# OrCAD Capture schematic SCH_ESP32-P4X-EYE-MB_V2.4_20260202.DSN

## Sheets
1 01_DESIGNBLOCK: title: ESP32-P4X-EYE-MB; rev: 2.4; note: 01_DESIGNBLOCK
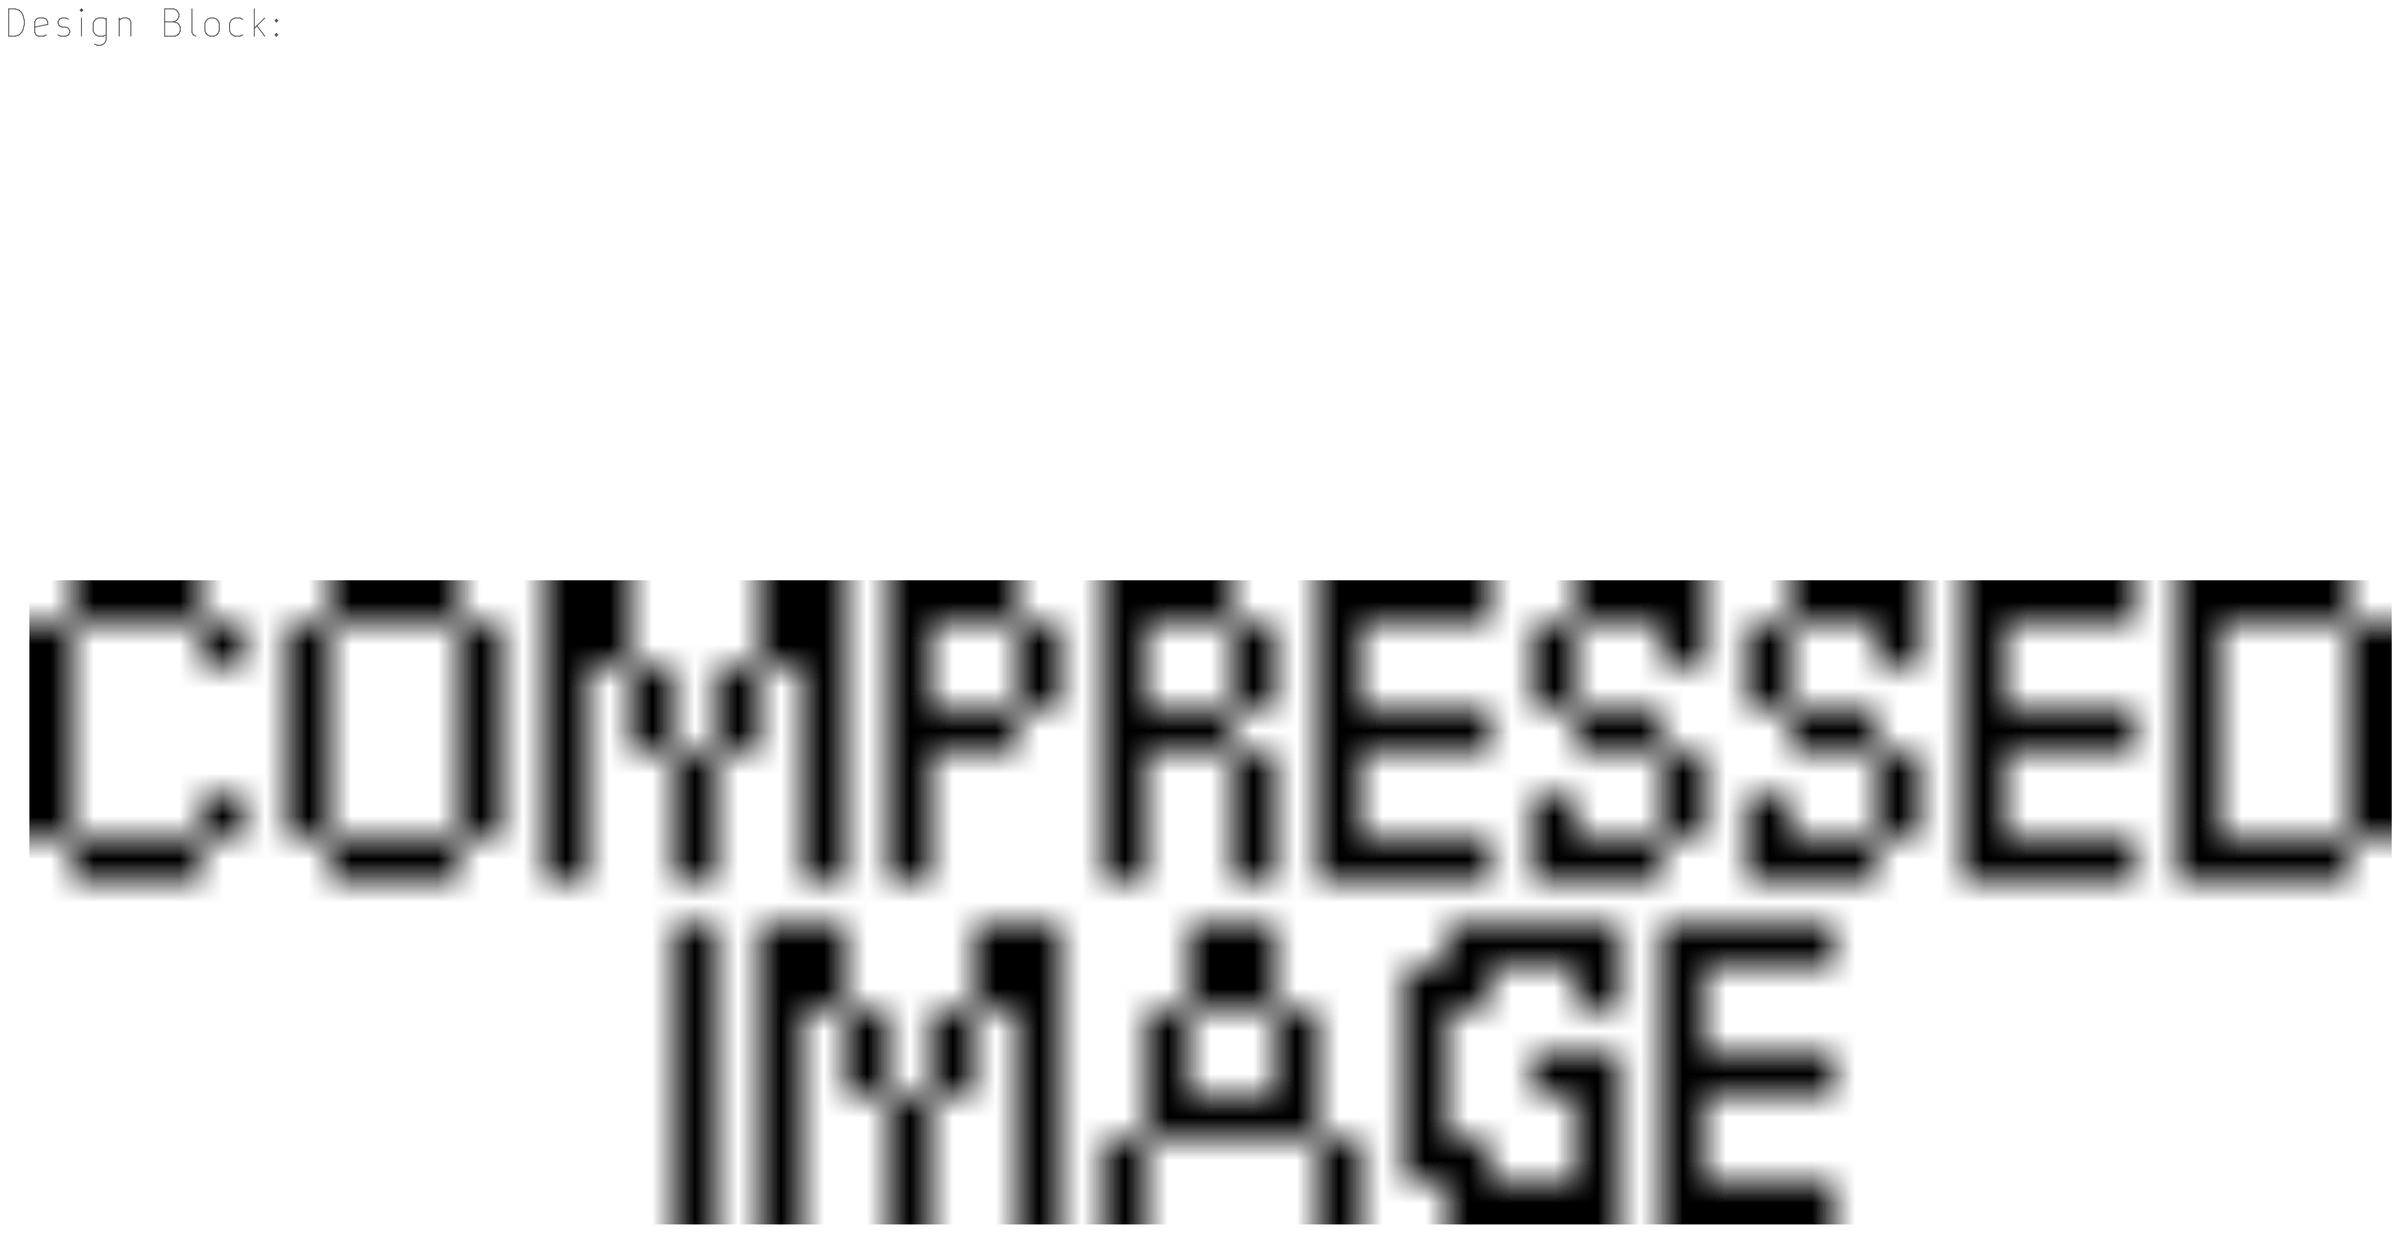
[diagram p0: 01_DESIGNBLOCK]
2 02_ESP32-P4: size C; note: 02_ESP32-P4X
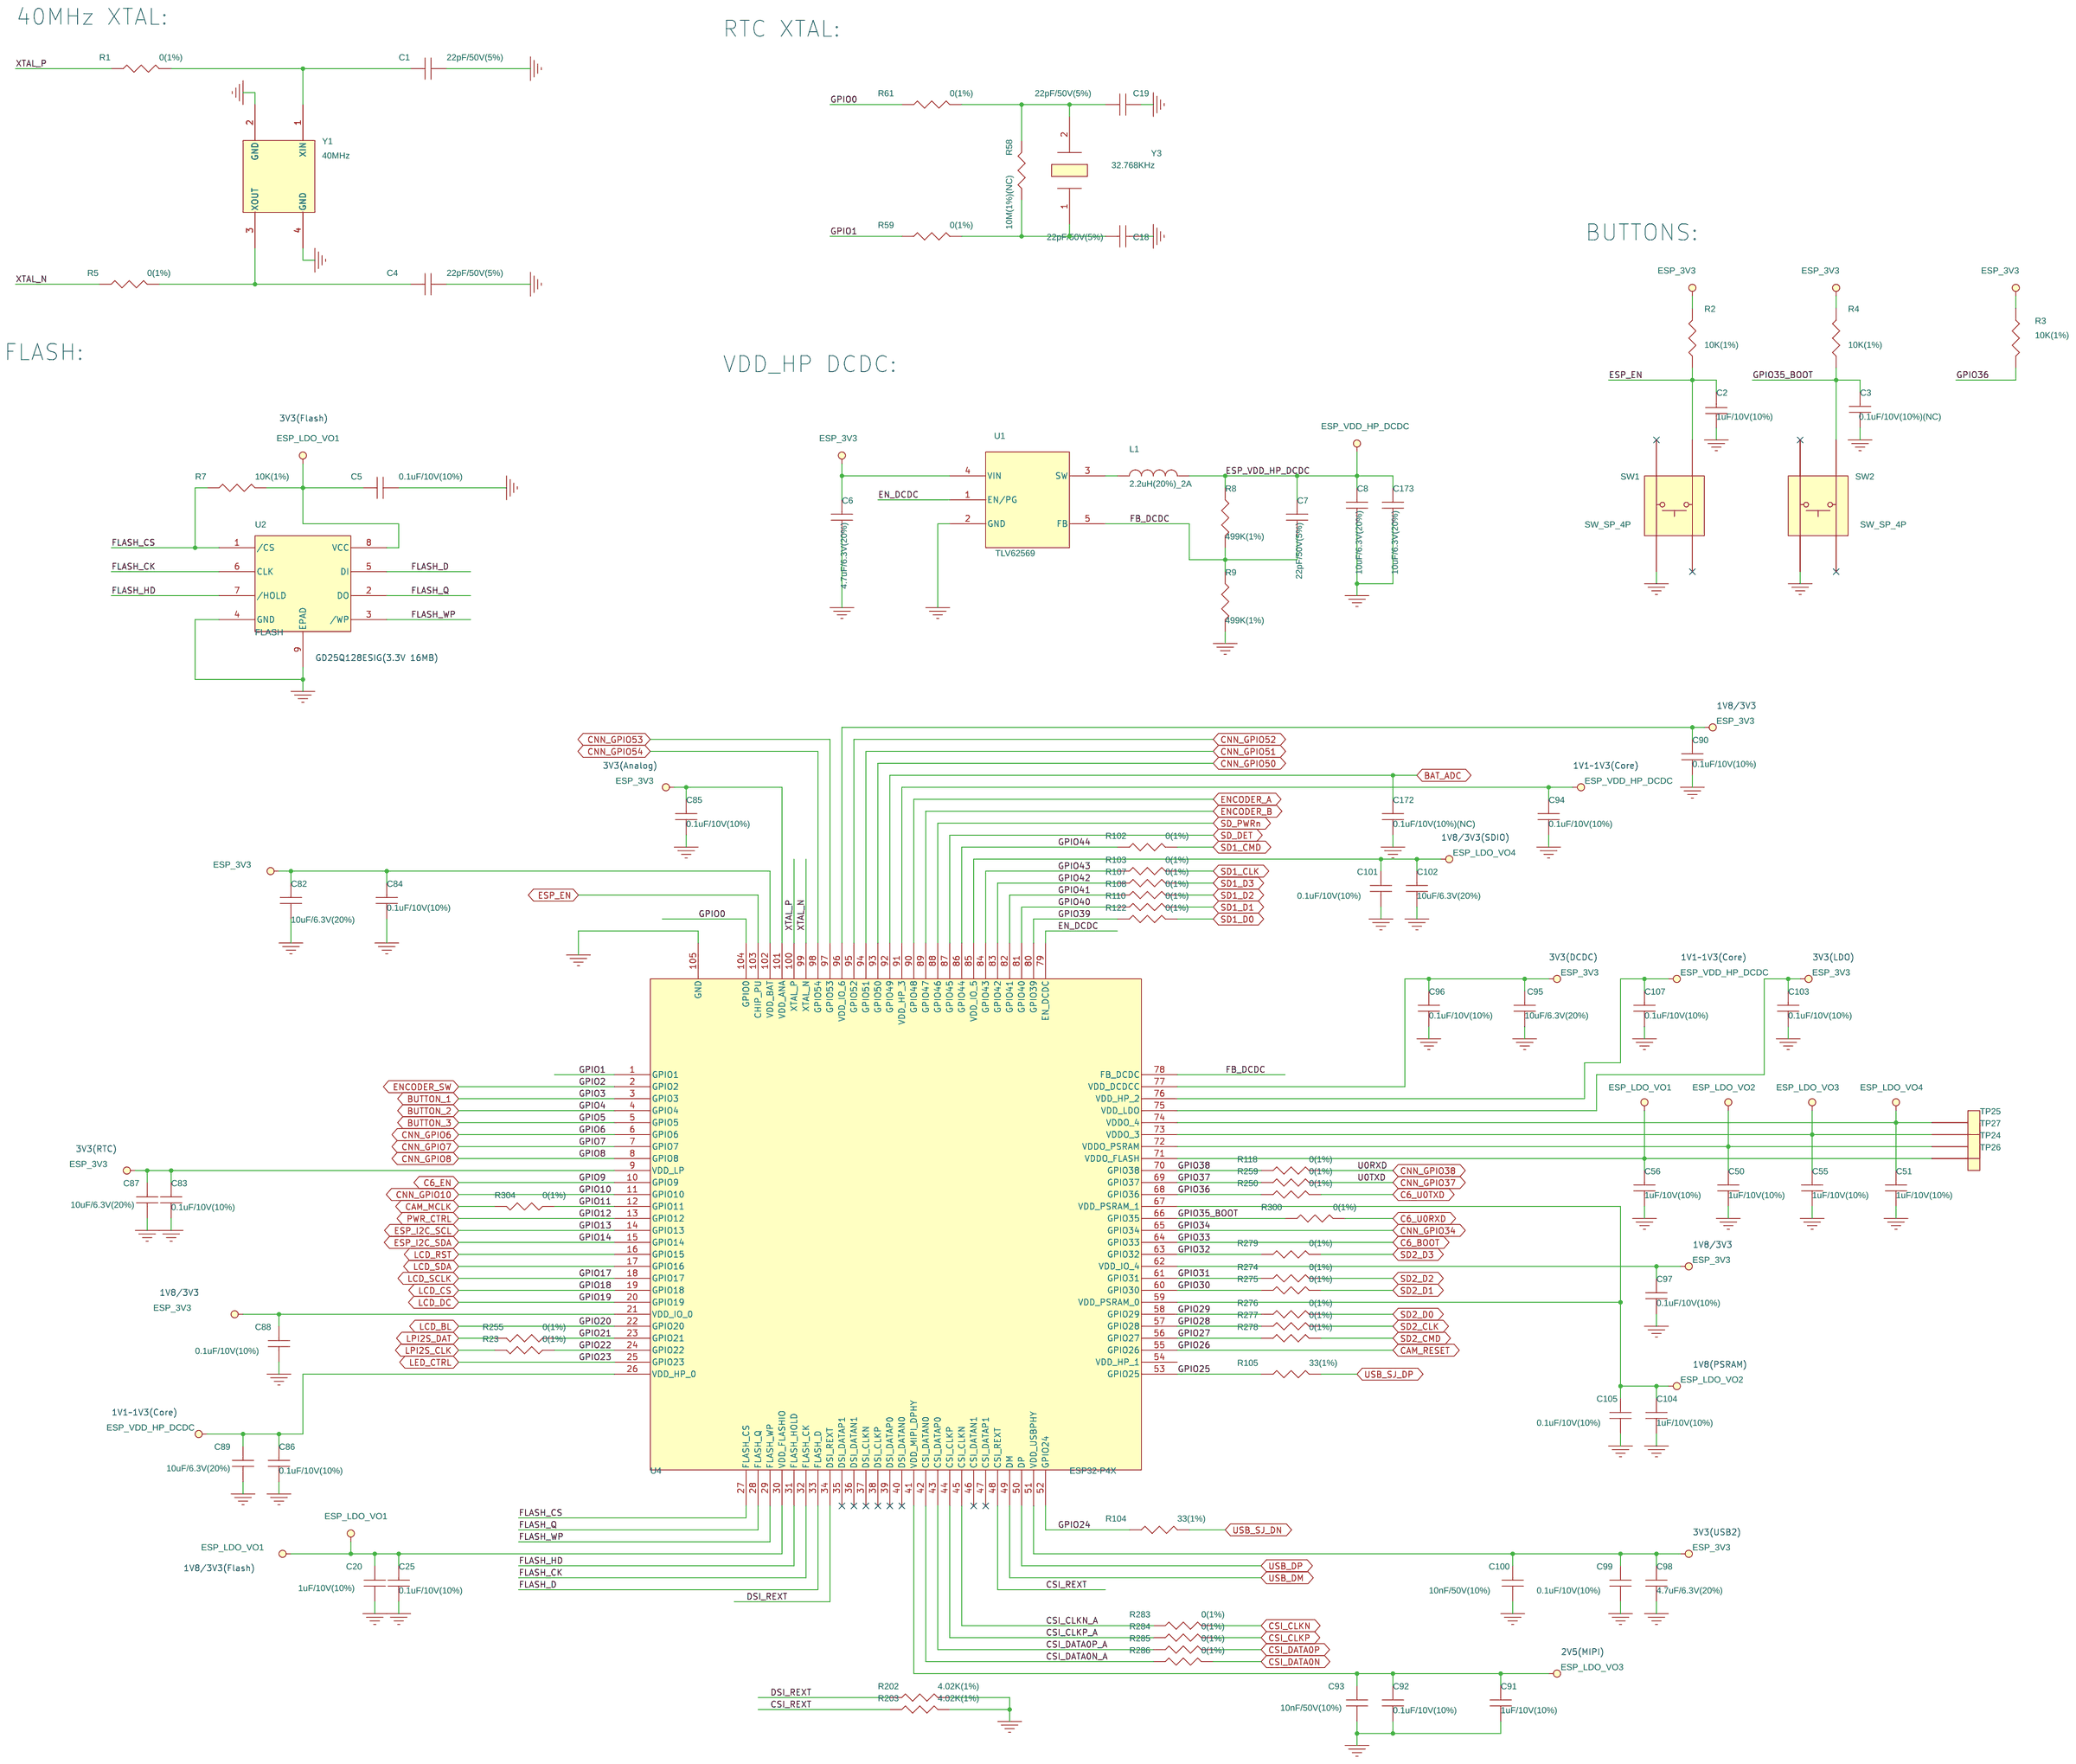
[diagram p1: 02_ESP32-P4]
3 03_INTERFACE: size C; note: 03_INTERFACE
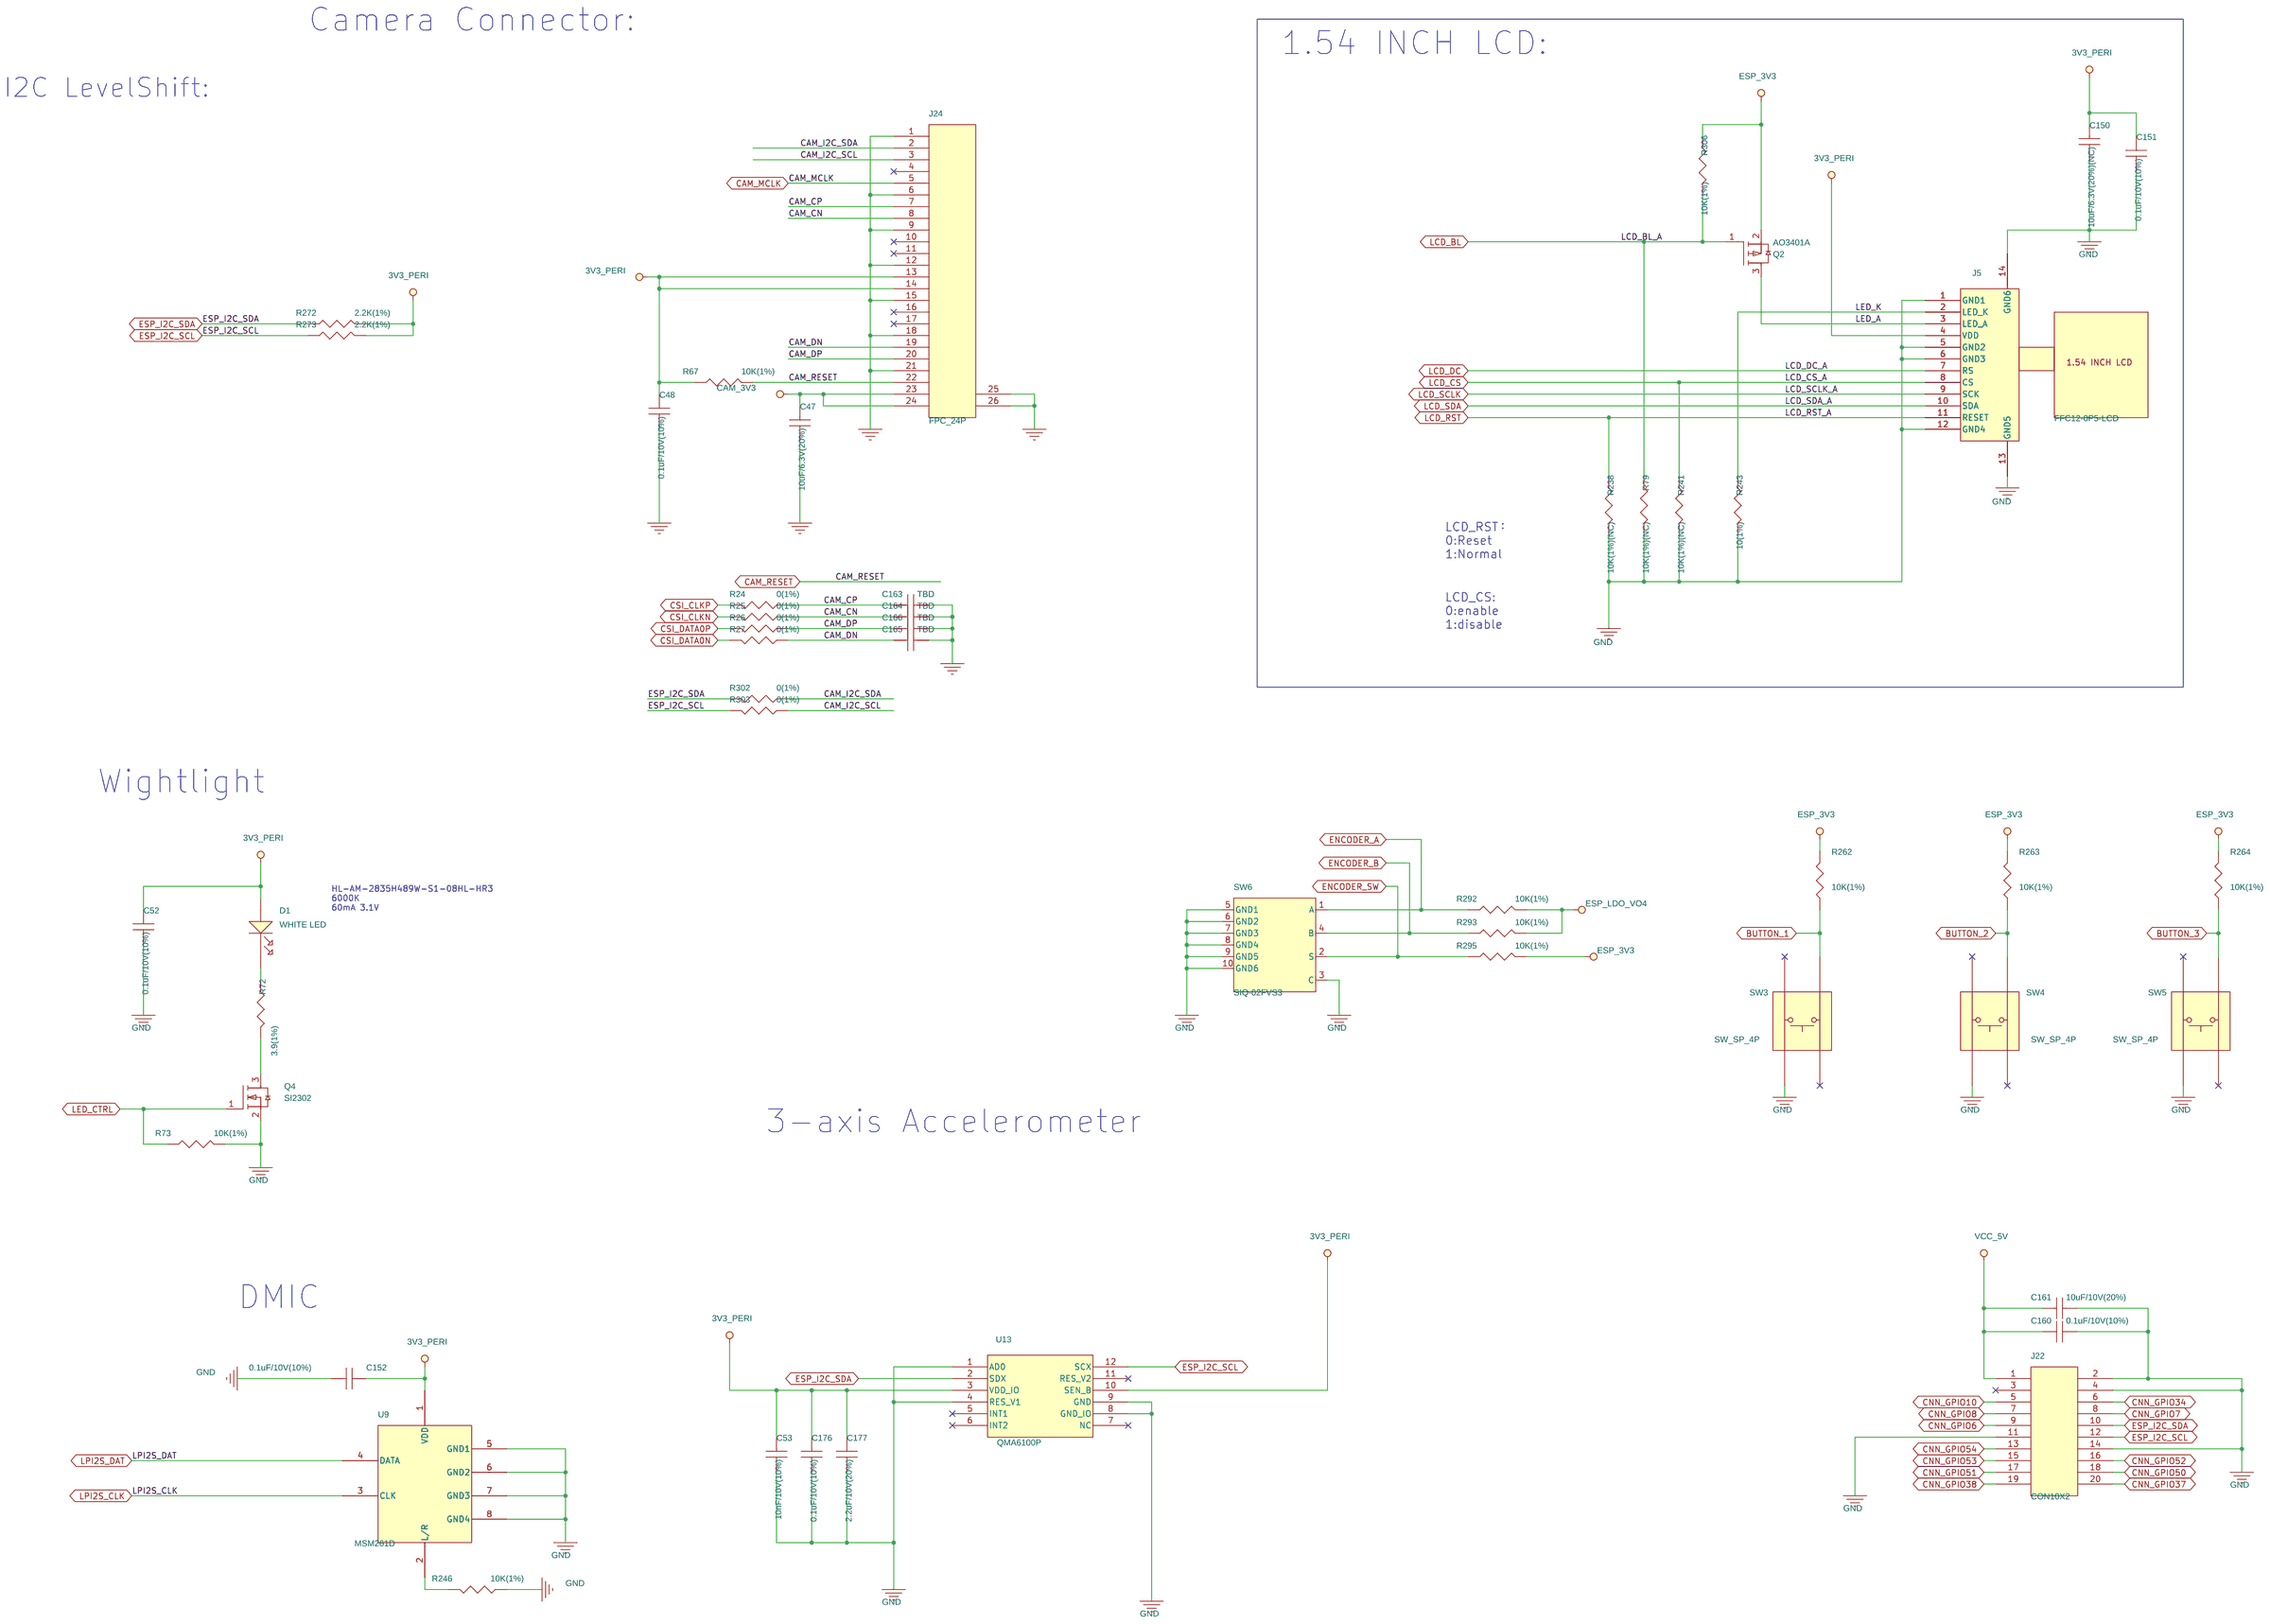
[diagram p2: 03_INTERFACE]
4 04_WiFi&BT_SDCard: size C; note: 04_WiFi&BT
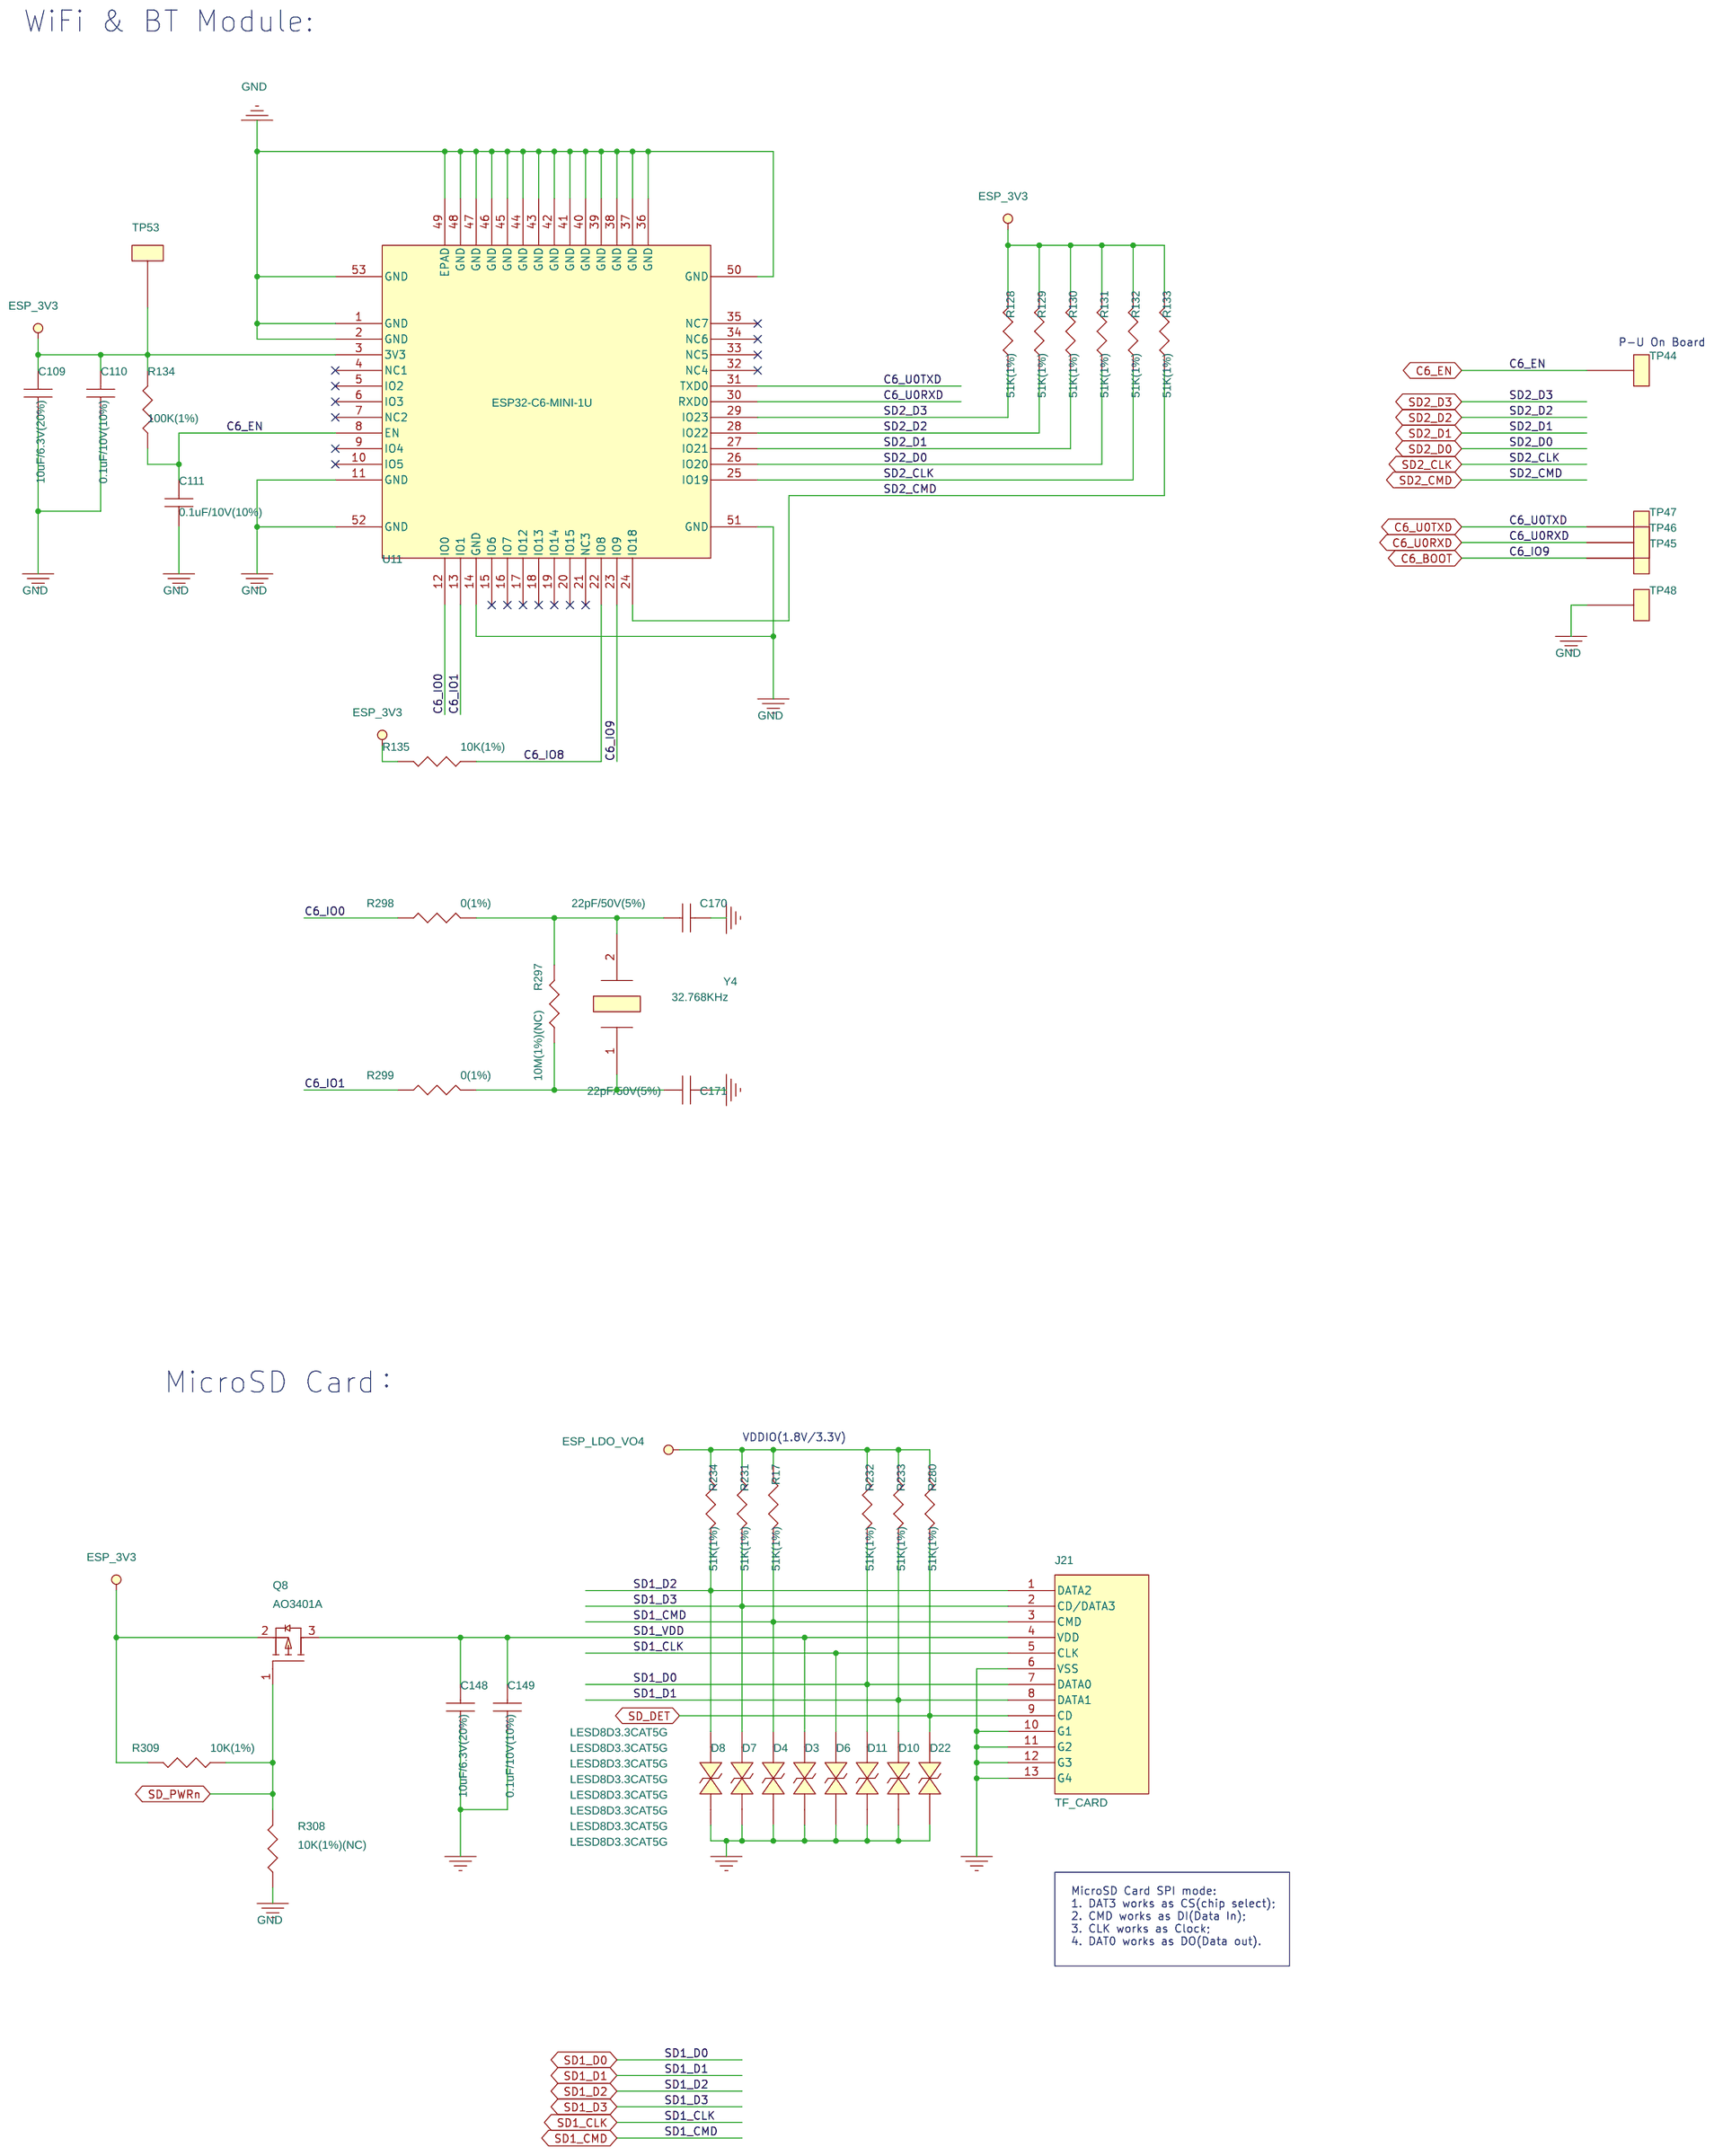
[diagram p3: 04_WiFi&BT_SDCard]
5 05_PWR_USB: size C; note: 05_PWR_USB
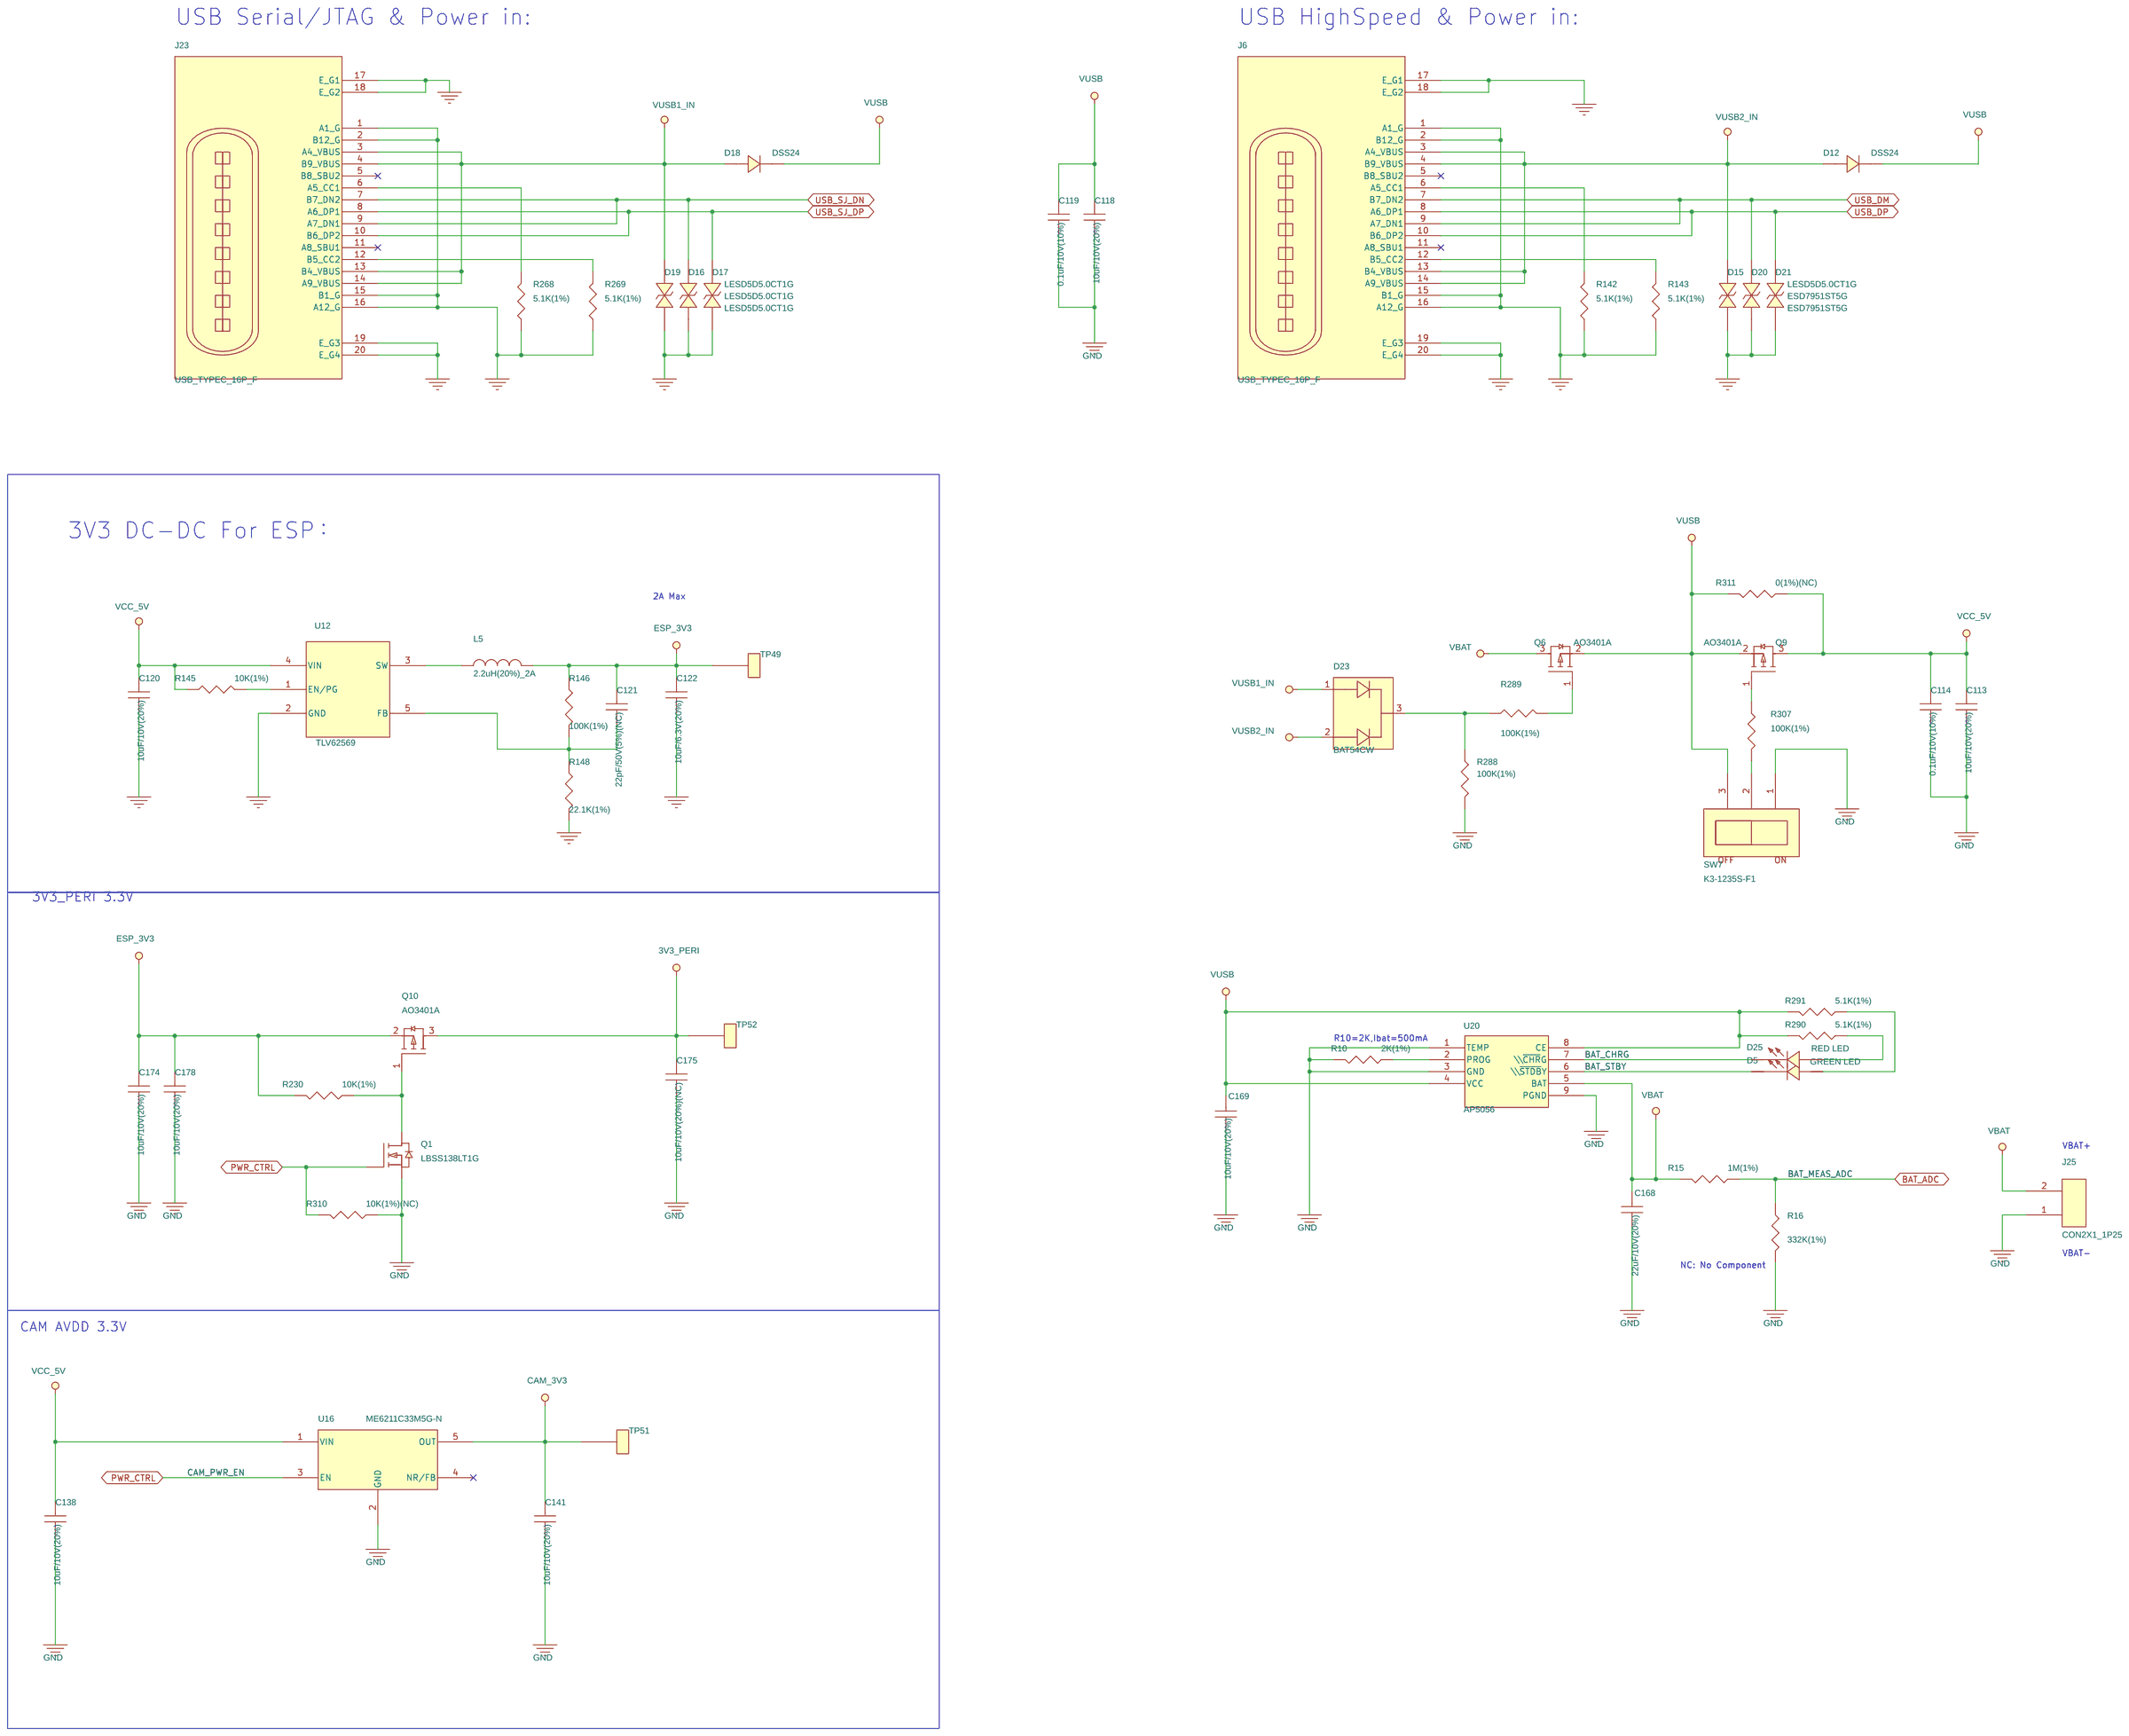
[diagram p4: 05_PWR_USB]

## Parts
sheet 02_ESP32-P4
C1  22pF/50V(5%)  [C0201]
C2  1uF/10V(10%)  [C0402]
C3  0.1uF/10V(10%)(NC)  [C0402]
C4  22pF/50V(5%)  [C0201]
C5  0.1uF/10V(10%)  [C0402]
C6  4.7uF/6.3V(20%)  [C0402]
C7  22pF/50V(5%)  [C0402]
C8  10uF/6.3V(20%)  [C0402]
C18  22pF/50V(5%)  [C0201]
C19  22pF/50V(5%)  [C0201]
C20  1uF/10V(10%)  [C0402]
C25  0.1uF/10V(10%)  [C0402]
C50  1uF/10V(10%)  [C0402]
C51  1uF/10V(10%)  [C0402]
C55  1uF/10V(10%)  [C0402]
C56  1uF/10V(10%)  [C0402]
C82  10uF/6.3V(20%)  [C0402]
C83  0.1uF/10V(10%)  [C0402]
C84  0.1uF/10V(10%)  [C0402]
C85  0.1uF/10V(10%)  [C0402]
C86  0.1uF/10V(10%)  [C0402]
C87  10uF/6.3V(20%)  [C0402]
C88  0.1uF/10V(10%)  [C0402]
C89  10uF/6.3V(20%)  [C0402]
C90  0.1uF/10V(10%)  [C0402]
C91  1uF/10V(10%)  [C0402]
C92  0.1uF/10V(10%)  [C0402]
C93  10nF/50V(10%)  [C0402]
C94  0.1uF/10V(10%)  [C0402]
C95  10uF/6.3V(20%)  [C0402]
C96  0.1uF/10V(10%)  [C0402]
C97  0.1uF/10V(10%)  [C0402]
C98  4.7uF/6.3V(20%)  [C0402]
C99  0.1uF/10V(10%)  [C0402]
C100  10nF/50V(10%)  [C0402]
C101  0.1uF/10V(10%)  [C0402]
C102  10uF/6.3V(20%)  [C0402]
C103  0.1uF/10V(10%)  [C0402]
C104  1uF/10V(10%)  [C0402]
C105  0.1uF/10V(10%)  [C0402]
C107  0.1uF/10V(10%)  [C0402]
C172  0.1uF/10V(10%)(NC)  [C0201]
C173  10uF/6.3V(20%)  [C0402]
L1  2.2uH(20%)_2A  [L2520]
R1  0(1%)  [R0201]
R2  10K(1%)  [R0201]
R3  10K(1%)  [R0201]
R4  10K(1%)  [R0201]
R5  0(1%)  [R0201]
R7  10K(1%)  [R0201]
R8  499K(1%)  [R0402]
R9  499K(1%)  [R0402]
R23  0(1%)  [R0201]
R58  10M(1%)(NC)  [R0201]
R59  0(1%)  [R0201]
R61  0(1%)  [R0201]
R102  0(1%)  [R0201]
R103  0(1%)  [R0201]
R104  33(1%)  [R0201]
R105  33(1%)  [R0201]
R107  0(1%)  [R0201]
R108  0(1%)  [R0201]
R110  0(1%)  [R0201]
R118  0(1%)  [R0201]
R122  0(1%)  [R0201]
R202  4.02K(1%)  [R0201]
R203  4.02K(1%)  [R0201]
R250  0(1%)  [R0201]
R255  0(1%)  [R0201]
R259  0(1%)  [R0201]
R274  0(1%)  [R0201]
R275  0(1%)  [R0201]
R276  0(1%)  [R0201]
R277  0(1%)  [R0201]
R278  0(1%)  [R0201]
R279  0(1%)  [R0201]
R283  0(1%)  [R0201]
R284  0(1%)  [R0201]
R285  0(1%)  [R0201]
R286  0(1%)  [R0201]
R300  0(1%)  [R0201]
R304  0(1%)  [R0201]
SW1  SW_SP_4P  [sw4-4p2x3p2x2p5-smt]
SW2  SW_SP_4P  [sw4-4p2x3p2x2p5-smt]
TP24  TESTPOINT  [TPC1]
TP25  TESTPOINT  [TPC1]
TP26  TESTPOINT  [TPC1]
TP27  TESTPOINT  [TPC1]
U1  TLV62569  [sot23_0P95_2P6]
U2  FLASH  [WSON8_1p27_6x5_e4x3p4]
U4  ESP32-P4X  [qfn104_0p35_10_e7p5_a]
Y1  40MHz  [XTAL3225]
Y3  32.768KHz  [XTAL3215_2P]
sheet 03_INTERFACE
C47  10uF/6.3V(20%)  [C0402]
C48  0.1uF/10V(10%)  [C0201]
C52  0.1uF/10V(10%)  [C0402]
C53  10nF/10V(10%)  [C0201]
C150  10uF/6.3V(20%)(NC)  [C0402]
C151  0.1uF/10V(10%)  [C0402]
C152  0.1uF/10V(10%)  [C0201]
C160  0.1uF/10V(10%)  [C0402]
C161  10uF/10V(20%)  [C0603]
C163  TBD  [C0201]
C164  TBD  [C0201]
C165  TBD  [C0201]
C166  TBD  [C0201]
C176  0.1uF/10V(10%)  [C0201]
C177  2.2uF/10V(20%)  [C0402]
D1  WHITE LED  [LED2835]
J5  FFC12-0P5-LCD  [FFC12_0P5_AFC24-S12FIC-00]
J22  CON10X2  [con10x2_2p54_smt_r]
J24  FPC_24P  [FFC24_0P5_FPC-05FB-24PH20]
Q2  AO3401A  [SOT23-3]
Q4  SI2302  [SOT23-3]
R24  0(1%)  [R0201]
R25  0(1%)  [R0201]
R26  0(1%)  [R0201]
R27  0(1%)  [R0201]
R67  10K(1%)  [R0201]
R72  3.9(1%)  [R0402]
R73  10K(1%)  [R0201]
R79  10K(1%)(NC)  [R0201]
R238  10K(1%)(NC)  [R0201]
R241  10K(1%)(NC)  [R0201]
R243  10(1%)  [R0402]
R246  10K(1%)  [R0201]
R262  10K(1%)  [R0201]
R263  10K(1%)  [R0201]
R264  10K(1%)  [R0201]
R272  2.2K(1%)  [R0201]
R273  2.2K(1%)  [R0201]
R292  10K(1%)  [R0201]
R293  10K(1%)  [R0201]
R295  10K(1%)  [R0201]
R302  0(1%)  [R0201]
R303  0(1%)  [R0201]
R306  10K(1%)  [R0201]
SW3  SW_SP_4P  [sw4-4p2x3p2x2p5-smt]
SW4  SW_SP_4P  [sw4-4p2x3p2x2p5-smt]
SW5  SW_SP_4P  [sw4-4p2x3p2x2p5-smt]
SW6  SIQ-02FVS3  [SIQ-02FVS3]
U9  MSM261D  [OCLGA-8]
U13  QMA6100P  [LGA12_0P5_2]
sheet 04_WiFi&BT_SDCard
C109  10uF/6.3V(20%)  [C0402]
C110  0.1uF/10V(10%)  [C0402]
C111  0.1uF/10V(10%)  [C0402]
C148  10uF/6.3V(20%)  [C0402]
C149  0.1uF/10V(10%)  [C0402]
C170  22pF/50V(5%)  [C0201]
C171  22pF/50V(5%)  [C0201]
D3  LESD8D3.3CAT5G  [SOD882]
D4  LESD8D3.3CAT5G  [SOD882]
D6  LESD8D3.3CAT5G  [SOD882]
D7  LESD8D3.3CAT5G  [SOD882]
D8  LESD8D3.3CAT5G  [SOD882]
D10  LESD8D3.3CAT5G  [SOD882]
D11  LESD8D3.3CAT5G  [SOD882]
D22  LESD8D3.3CAT5G  [SOD882]
J21  TF_CARD  [tf_carda]
Q8  AO3401A  [SOT23-3]
R17  51K(1%)  [R0201]
R128  51K(1%)  [R0201]
R129  51K(1%)  [R0201]
R130  51K(1%)  [R0201]
R131  51K(1%)  [R0201]
R132  51K(1%)  [R0201]
R133  51K(1%)  [R0201]
R134  100K(1%)  [R0201]
R135  10K(1%)  [R0201]
R231  51K(1%)  [R0201]
R232  51K(1%)  [R0201]
R233  51K(1%)  [R0201]
R234  51K(1%)  [R0201]
R280  51K(1%)  [R0201]
R297  10M(1%)(NC)  [R0201]
R298  0(1%)  [R0201]
R299  0(1%)  [R0201]
R308  10K(1%)(NC)  [R0201]
R309  10K(1%)  [R0201]
TP44  TESTPOINT  [TPC1]
TP45  TESTPOINT  [TPC1]
TP46  TESTPOINT  [TPC1]
TP47  TESTPOINT  [TPC1]
TP48  TESTPOINT  [TPC1]
TP53  TESTPOINT  [TPC1]
U11  ESP32-C6-MINI-1U  [ESP32-C6-MINI-1U]
Y4  32.768KHz  [XTAL3215_2P]
sheet 05_PWR_USB
C113  10uF/10V(20%)  [C0603]
C114  0.1uF/10V(10%)  [C0402]
C118  10uF/10V(20%)  [C0603]
C119  0.1uF/10V(10%)  [C0402]
C120  10uF/10V(20%)  [C0603]
C121  22pF/50V(5%)(NC)  [C0402]
C122  10uF/6.3V(20%)  [C0402]
C138  10uF/10V(20%)  [C0603]
C141  10uF/10V(20%)  [C0603]
C168  22uF/10V(20%)  [C0603]
C169  10uF/10V(20%)  [C0603]
C174  10uF/10V(20%)  [C0603]
C175  10uF/10V(20%)(NC)  [C0603]
C178  10uF/10V(20%)  [C0603]
D5  GREEN LED  [LED0603]
D12  DSS24  [SOD123FL]
D15  LESD5D5.0CT1G  [SOD523]
D16  LESD5D5.0CT1G  [SOD523]
D17  LESD5D5.0CT1G  [SOD523]
D18  DSS24  [SOD123FL]
D19  LESD5D5.0CT1G  [SOD523]
D20  ESD7951ST5G  [SOD882]
D21  ESD7951ST5G  [SOD882]
D23  BAT54CW  [SOT323]
D25  RED LED  [LED0603]
J6  USB_TYPEC_16P_F  [USB_TYPEC_16P_F]
J23  USB_TYPEC_16P_F  [USB_TYPEC_16P_F]
J25  CON2X1_1P25  [gh2_1p25_r]
L5  2.2uH(20%)_2A  [L2520]
Q1  LBSS138LT1G  [SOT23-3]
Q6  AO3401A  [SOT23-3]
Q9  AO3401A  [SOT23-3]
Q10  AO3401A  [SOT23-3]
R10  2K(1%)  [R0402]
R15  1M(1%)  [R0402]
R16  332K(1%)  [R0402]
R142  5.1K(1%)  [R0201]
R143  5.1K(1%)  [R0201]
R145  10K(1%)  [R0402]
R146  100K(1%)  [R0402]
R148  22.1K(1%)  [R0402]
R230  10K(1%)  [R0201]
R268  5.1K(1%)  [R0201]
R269  5.1K(1%)  [R0201]
R288  100K(1%)  [R0201]
R289  100K(1%)  [R0201]
R290  5.1K(1%)  [R0402]
R291  5.1K(1%)  [R0402]
R307  100K(1%)  [R0402]
R310  10K(1%)(NC)  [R0201]
R311  0(1%)(NC)  [R0603]
SW7  K3-1235S-F1  [SW3-9p1x3p5x5p5-smt]
TP49  TESTPOINT  [TPC1]
TP51  TESTPOINT  [TPC1]
TP52  TESTPOINT  [TPC1]
U12  TLV62569  [sot23_0P95_2P6]
U16  ME6211C33M5G-N  [SOT23-5]
U20  AP5056  [SOP8_1P27_4P9X3P9_E3P3X2P4]

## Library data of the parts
C1 C4 C7 C18 C19 C121 C170 C171 = CAPACITOR: Part Number: ES110412265200; Part Type: Capacitor
C2 C3 C5 C25 C83-C86 C88 C90 C92 C94 C96 C97 C99 C101 C103 C105 C107 C110 C149 C172 = CAPACITOR: Part Number: ES110451066200; Part Type: Capacitor
C6 C8 C20 C82 C87 C89 C91 C93 C95 C98 C100 C102 C104 C120 C122 C173 = CAP
C50 C51 C55 C56 C111 = CAPACITOR: Part Number: ES110461046100; Part Type: Capacitor
L1 L5 = INDUCTOR
R1 R5 R24-R27 R302-R304 = RESISTOR: Part Number: ES210400000000; Part Type: Resistor
R2-R4 R7 R67 R128-R135 R262-R264 R292 R293 R295 = RESISTOR: Part Number: ES210441000000; Part Type: Resistor
R8 R9 R23 R59 R61 R102-R105 R107 R108 R110 R118 R122 R146 R148 R202 R203 R243 R250 R255 R259 R272-R279 R283-R286 R298-R300 = RESISTOR
R58 R297 = RESISTOR: Part Number: ES210471000000; Part Type: Resistor
SW1-SW5 = SW_SP_4P
TP24-TP27 = TESTPOINT: Part Number: ES519900000000
U1 U12 = TLV62565
U2 = FLASH_EPAD
U4 = ESP32-P4_QFN104_ECO6
Y1 = XTAL
Y3 Y4 = XTAL_2P
C47 C48 C148 C160 C163-C166 = CAPACITOR
C52 = CAPACITOR: CODE12: ES11.04.510.2.6.2.00; Part Number: ES11045102620001; Part Type: Capacitor
C53 = CAPACITOR: CODE12: ES11.02.410.3.6.0.00; Part Number: ES11024103600001; Part Type: Capacitor
C150 C161 = CAPACITOR: CODE12: ES11.06.710.4.7.0.00; Part Number: ES11067104700001; Part Type: Capacitor
C114 C119 C151 = CAPACITOR: CODE12: ES11.04.510.3.6.2.00; Part Number: ES11045103620000; Part Type: Capacitor
C152 C168 C169 = CAP_NP
C176 = CAPACITOR: CODE12: ES11.02.510.3.6.1.00; Part Number: ES11025103610001; Part Type: Capacitor
C177 = CAPACITOR: CODE12: ES11.04.647.3.6.0.00; Part Number: ES11046473600001; Part Type: Capacitor
D1 = DIODE_LIGHT: Part Number: ES313400100000; Part Type: Diode
J5 = FFC12-0P5-LCD_3
J22 = CON10X2
J24 = FPC_24P
Q2 = PMOS: CODE12: ES31.46.0000.00.0.0; Part Number: ES31460000000000; Part Type: Transistor
Q4 = NMOS
R72 = RESISTOR: CODE12: ES21.02.1510.0.00.0; Part Number: ES21021510000001; Part Type: Resistor
R73 = RESISTOR: CODE12: ES21.02.4100.0.00.0; Part Number: ES21024100000001; Part Type: Resistor
R79 R238 R241 R306 = RESISTOR: CODE12: ES21.02.3200.0.00.0; Part Number: ES21023200000001; Part Type: Resistor
R10 R15 R16 R246 R288-R291 R307 = RESISTOR_0
SW6 = Encoder
U9 = NSM0418DT
U13 = QMA7981_0
C109 = CAPACITOR: Part Number: ES110671057000; Part Type: Capacitor
D3 D4 D6-D8 D10 D11 D22 = DIODE_BI_DIR: Part Number: ES313200100000; Part Type: Diode
J21 = TF_SD_SOCKET
Q8 Q10 = PMOS
R17 R231-R234 R280 = RESISTOR: Part Number: ES210445100000; Part Type: Resistor
R230 R308-R311 = RESISTOR: Part Number: ES210600000000; Part Type: Resistor
TP44-TP49 TP51-TP53 = TESTPOINT: CODE12: ES51.99.0010.00.00; Part Number: ES51990010000000
U11 = ESP32-C6-MINI-1
C113 C118 C138 C141 C174 C175 C178 = CAPACITOR: CODE12: ES11.06.710.4.6.0.00; Part Number: ES11067104600000; Part Type: Capacitor
D5 D25 = LED_1
D12 D18 = DIODE_S: CODE12: ES31.30.0020.00.0.0; Part Number: ES31300150000000; Part Type: Diode
D15-D17 D19-D21 = DIODE_BI_DIR: CODE12: ES31.32.0020.00.0.0; Part Number: ES31320020000000; Part Type: Diode
D23 = BAT54C_0
J6 J23 = USB_TYPEC_16P_F: CODE12: ES52.22.0020.00.00; Part Number: ES52220020000000; Part Type: Connector
J25 = CON2X1
Q1 = MOSFET_EN_DGS_0
Q6 Q9 = PMOS_0: CODE12: ES31.46.0000.00.0.0; Part Number: ES31460000000000; Part Type: Transistor
R142 R143 R268 R269 = RESISTOR: Part Number: ES210435100000; Part Type: Resistor
R145 = RESISTOR: Part Number: ES210451000000; Part Type: Resistor
SW7 = SS-12D10L3
U16 = LDO_SOT23-5_3: CODE12: ES41.14.02.07.00.00; Part Number: ES41140207000000; Part Type: Power ICs
U20 = AP5056

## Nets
3V3_PERI: C48.1 C52.1 C53.1 C150.1 C151.1 C152.1 C175.1 C176.1 C177.1 D1.1(ANODE) J5.4(VDD) J24.13 J24.14 Q10.3(D) R67.1 R272.2 R273.2 TP52.1 U9.1(VDD) U13.3(VDD_IO) U13.10(SEN_B)
GND: C1.2 C2.1 C3.2 C4.2 C5.2 C6.2 C8.2 C18.2 C19.2 C20.2 C25.2 C47.2 C48.2 C50.2 C51.2 C52.2 C53.2 C55.2 C56.2 C82.2 C83.2 C84.2 C85.2 C86.2 C87.2 C88.2 C89.2 C90.2 C91.2 C92.2 C93.2 C94.2 C95.2 C96.2 C97.2 C98.2 C99.2 C100.2 C101.2 C102.2 C103.2 C104.2 C105.2 C107.2 C109.2 C110.2 C111.2 C113.2 C114.2 C118.2 C119.2 C120.2 C122.2 C138.2 C141.2 C148.2 C149.2 C150.2 C151.2 C152.2 C160.2 C161.2 C163.2 C164.2 C165.2 C166.2 C168.1 C169.1 C170.2 C171.2 C172.2 C173.2 C174.2 C175.2 C176.2 C177.2 C178.2 D3.1 D4.1 D6.1 D7.1 D8.1 D10.1 D11.1 D15.1 D16.1 D17.1 D19.1 D20.1 D21.1 D22.1 J5.1(GND1) J5.5(GND2) J5.6(GND3) J5.12(GND4) J5.13(GND5) J5.14(GND6) J6.1(A1_G) J6.2(B12_G) J6.15(B1_G) J6.16(A12_G) J6.17(E_G1) J6.18(E_G2) J6.19(E_G3) J6.20(E_G4) J21.6(VSS) J21.10(G1) J21.11(G2) J21.12(G3) J21.13(G4) J22.2 J22.4 J22.11 J22.14 J23.1(A1_G) J23.2(B12_G) J23.15(B1_G) J23.16(A12_G) J23.17(E_G1) J23.18(E_G2) J23.19(E_G3) J23.20(E_G4) J24.1 J24.6 J24.9 J24.12 J24.15 J24.18 J24.21 J24.25 J24.26 J25.1 Q1.2(S) Q4.2(S) R9.2 R10.2 R16.2 R73.2 R79.2 R142.1 R143.1 R148.2 R202.2 R203.2 R238.2 R241.2 R243.2 R246.1 R268.1 R269.1 R288.2 R308.1 R310.1 SW1.1 SW2.1 SW3.1 SW4.1 SW5.1 SW6.3(C) SW6.5(GND1) SW6.6(GND2) SW6.7(GND3) SW6.8(GND4) SW6.9(GND5) SW6.10(GND6) SW7.1 TP48.1 U1.2(GND) U2.4(GND) U2.9(EPAD) U4.105(GND) U9.5(GND1) U9.6(GND2) U9.7(GND3) U9.8(GND4) U11.1(GND) U11.2(GND) U11.11(GND) U11.14(GND) U11.36(GND) U11.37(GND) U11.38(GND) U11.39(GND) U11.40(GND) U11.41(GND) U11.42(GND) U11.43(GND) U11.44(GND) U11.45(GND) U11.46(GND) U11.47(GND) U11.48(GND) U11.49(EPAD) U11.50(GND) U11.51(GND) U11.52(GND) U11.53(GND) U12.2(GND) U13.1(AD0) U13.4(RES_V1) U13.8(GND_IO) U13.9(GND) U16.2(GND) U20.1(TEMP) U20.3(GND) U20.9(PGND) Y1.2(GND) Y1.4(GND)
VBAT: C168.2 J25.2 Q6.3(D) R15.2 U20.5(BAT)
VCC_5V: C113.1 C114.1 C120.1 C138.1 C160.1 C161.1 J22.1 Q9.3(D) R145.1 R311.1 U12.4(VIN) U16.1(VIN)
VDD_HP_1: U4.54(VDD_HP_1)
BAT_ADC: C172.1 R15.1 R16.1 U4.92(GPIO49)
BAT_CHRG: D25.2(CATHODE) U20.7(\\~{CHR}G)
BAT_STBY: D5.2(CATHODE) U20.6(\\~{STDB}Y)
BUTTON_1: R262.1 SW3.3 U4.3(GPIO3)
BUTTON_2: R263.1 SW4.3 U4.4(GPIO4)
BUTTON_3: R264.1 SW5.3 U4.5(GPIO5)
C6_BOOT: TP45.1 U4.64(GPIO33) U11.23(IO9)
C6_EN: C111.1 R134.1 TP44.1 U4.10(GPIO9) U11.8(EN)
C6_IO0: R298.1 U11.12(IO0)
C6_IO1: R299.1 U11.13(IO1)
C6_IO8: R135.1 U11.22(IO8)
C6_U0RXD: R300.2 TP46.1 U11.30(RXD0)
C6_U0TXD: R250.2 TP47.1 U11.31(TXD0)
CAM_3V3: C47.1 C141.1 J24.23 J24.24 TP51.1 U16.5(OUT)
CAM_CN: C164.1 J24.8 R25.1
CAM_CP: C163.1 J24.7 R24.1
CAM_DN: C165.1 J24.19 R27.1
CAM_DP: C166.1 J24.20 R26.1
CAM_I2C_SCL: J24.3 R303.1
CAM_I2C_SDA: J24.2 R302.1
CAM_MCLK: J24.5 R304.2
CAM_RESET: J24.22 R67.2 U4.55(GPIO26)
CNN_GPIO6: J22.9 U4.6(GPIO6)
CNN_GPIO7: J22.8 U4.7(GPIO7)
CNN_GPIO8: J22.7 U4.8(GPIO8)
CNN_GPIO10: J22.5 U4.11(GPIO10)
CNN_GPIO34: J22.6 U4.65(GPIO34)
CNN_GPIO37: J22.20 R259.2
CNN_GPIO38: J22.19 R118.2
CNN_GPIO50: J22.18 U4.93(GPIO50)
CNN_GPIO51: J22.17 U4.94(GPIO51)
CNN_GPIO52: J22.16 U4.95(GPIO52)
CNN_GPIO53: J22.15 U4.97(GPIO53)
CNN_GPIO54: J22.13 U4.98(GPIO54)
CSI_CLKN: R25.2 R283.2
CSI_CLKN_A: R283.1 U4.45(CSI_CLKN)
CSI_CLKP: R24.2 R284.2
CSI_CLKP_A: R284.1 U4.44(CSI_CLKP)
CSI_DATA0N: R27.2 R286.2
CSI_DATA0N_A: R286.1 U4.42(CSI_DATAN0)
CSI_DATA0P: R26.2 R285.2
CSI_DATA0P_A: R285.1 U4.43(CSI_DATAP0)
CSI_REXT: R203.1 U4.48(CSI_REXT)
DSI_REXT: R202.1 U4.34(DSI_REXT)
EN_DCDC: U1.1(EN/PG) U4.79(EN_DCDC)
ENCODER_A: R292.1 SW6.1(A) U4.90(GPIO48)
ENCODER_B: R293.1 SW6.4(B) U4.89(GPIO47)
ENCODER_SW: R295.1 SW6.2(S) U4.2(GPIO2)
ESP_3V3: C6.1 C82.1 C83.1 C84.1 C85.1 C87.1 C88.1 C90.1 C95.1 C96.1 C97.1 C98.1 C99.1 C100.1 C103.1 C109.1 C110.1 C121.1 C122.1 C174.1 C178.1 L5.2 Q2.2(S) Q8.2(S) Q10.2(S) R2.2 R3.1 R4.2 R128.1 R129.1 R130.1 R131.1 R132.1 R133.1 R134.2 R135.2 R146.1 R230.2 R262.2 R263.2 R264.2 R295.2 R306.1 R309.2 TP49.1 TP53.1 U1.4(VIN) U4.9(VDD_LP) U4.21(VDD_IO_0) U4.51(VDD_USBPHY) U4.62(VDD_IO_4) U4.75(VDD_LDO) U4.77(VDD_DCDCC) U4.96(VDD_IO_6) U4.101(VDD_ANA) U4.102(VDD_BAT) U11.3(3V3)
ESP_EN: C2.2 R2.1 SW1.3 U4.103(CHIP_PU)
ESP_I2C_SCL: J22.12 R273.1 R303.2 U4.14(GPIO13) U13.12(SCX)
ESP_I2C_SDA: J22.10 R272.1 R302.2 U4.15(GPIO14) U13.2(SDX)
ESP_LDO_VO1: C5.1 C20.1 C25.1 C56.1 R7.2 TP26.1 U2.8(VCC) U4.30(VDD_FLASHIO) U4.71(VDDO_FLASH)
ESP_LDO_VO2: C50.1 C104.1 C105.1 TP24.1 U4.59(VDD_PSRAM_0) U4.67(VDD_PSRAM_1) U4.72(VDDO_PSRAM)
ESP_LDO_VO3: C55.1 C91.1 C92.1 C93.1 TP27.1 U4.41(VDD_MIPI_DPHY) U4.73(VDDO_3)
ESP_LDO_VO4: C51.1 C101.1 C102.1 R17.1 R231.1 R232.1 R233.1 R234.1 R280.1 R292.2 R293.2 TP25.1 U4.74(VDDO_4) U4.85(VDD_IO_5)
ESP_VDD_HP: C7.1 C8.1 C86.1 C89.1 C94.1 C107.1 C173.1 L1.2 R8.1 U4.26(VDD_HP_0) U4.76(VDD_HP_2) U4.91(VDD_HP_3)
FB_DCDC: C7.2 R8.2 R9.1 U1.5(FB) U4.78(FB_DCDC)
FLASH_CK: U2.6(CLK) U4.32(FLASH_CK)
FLASH_CS: R7.1 U2.1(/CS) U4.27(FLASH_CS)
FLASH_D: U2.5(DI) U4.33(FLASH_D)
FLASH_HD: U2.7(/HOLD) U4.31(FLASH_HOLD)
FLASH_Q: U2.2(DO) U4.28(FLASH_Q)
FLASH_WP: U2.3(/WP) U4.29(FLASH_WP)
GPIO0: R61.1 U4.104(GPIO0)
GPIO1: R59.1 U4.1(GPIO1)
GPIO11: R304.1 U4.12(GPIO11)
GPIO21: R255.1 U4.23(GPIO21)
GPIO22: R23.1 U4.24(GPIO22)
GPIO24: R104.1 U4.52(GPIO24)
GPIO25: R105.1 U4.53(GPIO25)
GPIO27: R278.1 U4.56(GPIO27)
GPIO28: R277.1 U4.57(GPIO28)
GPIO29: R276.1 U4.58(GPIO29)
GPIO30: R275.1 U4.60(GPIO30)
GPIO31: R274.1 U4.61(GPIO31)
GPIO32: R279.1 U4.63(GPIO32)
GPIO35_BOOT: C3.1 R4.1 R300.1 SW2.3 U4.66(GPIO35)
GPIO36: R3.2 R250.1 U4.68(GPIO36)
GPIO37: R259.1 U4.69(GPIO37)
GPIO38: R118.1 U4.70(GPIO38)
GPIO39: R122.1 U4.80(GPIO39)
GPIO40: R110.1 U4.81(GPIO40)
GPIO41: R108.1 U4.82(GPIO41)
GPIO42: R107.1 U4.83(GPIO42)
GPIO43: R103.1 U4.84(GPIO43)
GPIO44: R102.1 U4.86(GPIO44)
LCD_BL: Q2.1(G) R79.1 R306.2 U4.22(GPIO20)
LCD_CS: J5.8(CS) R241.1 U4.19(GPIO18)
LCD_DC: J5.7(RS) U4.20(GPIO19)
LCD_RST: J5.11(RESET) R238.1 U4.16(GPIO15)
LCD_SCLK: J5.9(SCK) U4.18(GPIO17)
LCD_SDA: J5.10(SDA) U4.17(GPIO16)
LED_A: J5.3(LED_A) Q2.3(D)
LED_CTRL: Q4.1(G) R73.1 U4.25(GPIO23)
LED_K: J5.2(LED_K) R243.1
LPI2S_CLK: R23.2 U9.3(CLK)
LPI2S_DAT: R255.2 U9.4(DATA)
PWR_CTRL: Q1.1(G) R310.2 U4.13(GPIO12) U16.3(EN)
SD1_CLK: D6.2 J21.5(CLK) R103.2
SD1_CMD: D4.2 J21.3(CMD) R17.2 R102.2
SD1_D0: D11.2 J21.7(DATA0) R122.2 R232.2
SD1_D1: D10.2 J21.8(DATA1) R110.2 R233.2
SD1_D2: D8.2 J21.1(DATA2) R108.2 R234.2
SD1_D3: D7.2 J21.2(CD/DATA3) R107.2 R231.2
SD1_VDD: C148.1 C149.1 D3.2 J21.4(VDD) Q8.3(D)
SD2_CLK: R132.2 R277.2 U11.25(IO19)
SD2_CMD: R133.2 R278.2 U11.24(IO18)
SD2_D0: R131.2 R276.2 U11.26(IO20)
SD2_D1: R130.2 R275.2 U11.27(IO21)
SD2_D2: R129.2 R274.2 U11.28(IO22)
SD2_D3: R128.2 R279.2 U11.29(IO23)
SD_DET: D22.2 J21.9(CD) R280.2 U4.87(GPIO45)
SD_PWRn: Q8.1(G) R308.2 R309.1 U4.88(GPIO46)
USB_DM: D20.2 J6.7(B7_DN2) J6.9(A7_DN1) U4.49(DM)
USB_DP: D21.2 J6.8(A6_DP1) J6.10(B6_DP2) U4.50(DP)
USB_SJ_DN: D16.2 J23.7(B7_DN2) J23.9(A7_DN1) R104.2
USB_SJ_DP: D17.2 J23.8(A6_DP1) J23.10(B6_DP2) R105.2
VUSB: C118.1 C119.1 C169.2 D12.2(K) D18.2(K) Q6.2(S) Q9.2(S) R290.2 R291.2 R311.2 SW7.3 U20.4(VCC) U20.8(CE)
VUSB1_IN: D18.1(A) D19.2 D23.1 J23.3(A4_VBUS) J23.4(B9_VBUS) J23.13(B4_VBUS) J23.14(A9_VBUS)
VUSB2_IN: D12.1(A) D15.2 D23.2 J6.3(A4_VBUS) J6.4(B9_VBUS) J6.13(B4_VBUS) J6.14(A9_VBUS)
XTAL_N: R5.1 U4.99(XTAL_N)
XTAL_P: R1.1 U4.100(XTAL_P)
N16934509: C1.1 R1.2 Y1.1(XIN)
N16934523: C4.1 R5.2 Y1.3(XOUT)
N18193822: L1.1 U1.3(SW)
N18255493: J6.6(A5_CC1) R142.2
N18255499: J6.12(B5_CC2) R143.2
N18262730: C121.2 R146.2 R148.1 U12.5(FB)
N18262777: R145.2 U12.1(EN/PG)
N18262785: L5.1 U12.3(SW)
N18700058: D1.2(CATHODE) R72.1
N18700064: Q4.3(D) R72.2
N18877972: R246.2 U9.2(L/R)
N18902905: J23.6(A5_CC1) R268.2
N18902911: J23.12(B5_CC2) R269.2
N19010219: D23.3 R288.1 R289.1
N19010303: Q6.1(G) R289.2
N19013156: R10.1 U20.2(PROG)
N19013226: D25.1(ANODE) R290.1
N19013232: D5.1(ANODE) R291.1
N19026853: C19.1 R58.1 R61.2 Y3.2
N19026868: C18.1 R58.2 R59.2 Y3.1
N19027177: C170.1 R297.1 R298.2 Y4.2
N19027184: C171.1 R297.2 R299.2 Y4.1
N19080261: Q9.1(G) R307.1
N19080264: R307.2 SW7.2
N19083043: Q1.3(D) Q10.1(G) R230.1

Not connected (* = marked no-connect by the designer): J6 5(B8_SBU2)* 11(A8_SBU1)*; J22 3*; J23 5(B8_SBU2)* 11(A8_SBU1)*; J24 4* 10* 11* 16* 17*; SW1 2* 4*; SW2 2* 4*; SW3 2* 4*; SW4 2* 4*; SW5 2* 4*; U4 35(DSI_DATAP1)* 36(DSI_DATAN1)* 37(DSI_CLKN)* 38(DSI_CLKP)* 39(DSI_DATAP0)* 40(DSI_DATAN0)* 46(CSI_DATAN1)* 47(CSI_DATAP1)*; U11 4(NC1)* 5(IO2)* 6(IO3)* 7(NC2)* 9(IO4)* 10(IO5)* 15(IO6)* 16(IO7)* 17(IO12)* 18(IO13)* 19(IO14)* 20(IO15)* 21(NC3)* 32(NC4)* 33(NC5)* 34(NC6)* 35(NC7)*; U13 5(INT1)* 6(INT2)* 7(NC)* 11(RES_V2)*; U16 4(NR/FB)*

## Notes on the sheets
sheet 1
- Design Block:
sheet 2
- 40MHz XTAL:
- RTC XTAL:
- BUTTONS:
- FLASH:
- VDD_HP DCDC:
- 3V3(Flash)
- GD25Q128ESIG(3.3V 16MB)
- 1V8/3V3
- 3V3(Analog)
- 1V1~1V3(Core)
- 1V8/3V3(SDIO)
- 3V3(DCDC)
- 1V1~1V3(Core)
- 3V3(LDO)
- 3V3(RTC)
- 1V8/3V3
- 1V8/3V3
- 1V8(PSRAM)
- 1V1~1V3(Core)
- 3V3(USB2)
- 1V8/3V3(Flash)
- 2V5(MIPI)
sheet 3
- Camera Connector:
- 1.54 INCH LCD:
- I2C LevelShift:
- LCD_RST：
  0:Reset
  1:Normal
- LCD_CS:
  0:enable
  1:disable
- Wightlight
- HL-AM-2835H489W-S1-08HL-HR3
  6000K
  60mA 3.1V
- 3-axis Accelerometer
- DMIC
sheet 4
- WiFi & BT Module:
- P-U On Board
- MicroSD Card：
- VDDIO(1.8V/3.3V)
- MicroSD Card SPI mode:
  1. DAT3 works as CS(chip select);
  2. CMD works as DI(Data In);
  3. CLK works as Clock;
  4. DAT0 works as DO(Data out).
sheet 5
- USB Serial/JTAG & Power in:
- USB HighSpeed & Power in:
- 3V3 DC-DC For ESP：
- 2A Max
- 3V3_PERI 3.3V
- R10=2K,Ibat=500mA
- VBAT+
- VBAT-
- NC: No Component
- CAM AVDD 3.3V
